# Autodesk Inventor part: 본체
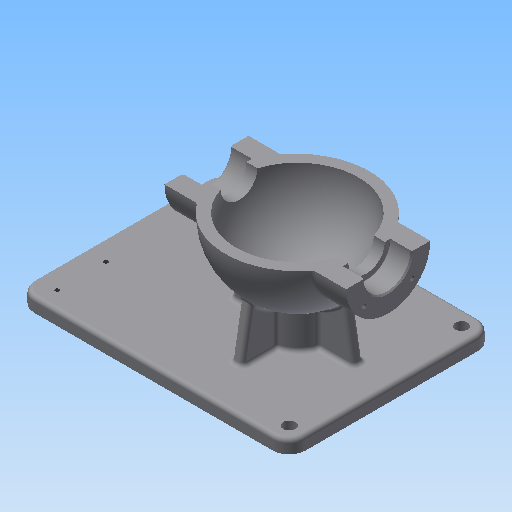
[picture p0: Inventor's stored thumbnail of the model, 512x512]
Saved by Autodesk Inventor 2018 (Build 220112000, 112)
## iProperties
Created: 2015-12
Part Number: 본체
Material: 일반
Document SubType Name: Modeling
Designer: mduedu
Density: 1 g/cm^3
Mass: 491.008 g
Surface Area: 1128.56 cm^2
Volume: 491.008 cm^3
Appearance: 기본값
Author: mduedu
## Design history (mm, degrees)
sketch "스케치1"
  geometry: L1 (-53, 0)-(53, 0); A1 r 53 centre (0, 0) between (53, 0) and (-53, 0); 2 further points
  constraints: 2 coincident, 2 end point, 2 point on circle, 1 centre point, 1 horizontal, 1 midpoint
  dimensions: "d0" = 53 radius of A1
revolve "회전1" sketch "스케치1" stored, may be unused: angle "d2" = 90 deg
feature "쉘1" dims "d11" = 8
node "작업 평면1"
sketch "스케치2"
  geometry: C1 r 31 at (0, 0); 1 further point
  constraints: 1 centre point, 1 coincident
  dimensions: "d4" = 62 diameter of C1
extrude "돌출1" join sketch "스케치2" stored distance "d5" = 10; taper "d6" = 0 deg
hole "구멍1" diameter "d14" = 35; stored, may be unused: countersink angle "d18" = 90 deg, drill point angle "d20" = 0 deg; dims "d12" = 10, "d13" = 10, "d15" = 6, "d16" = 4, "d17" = 2, "d19" = 16
hole "구멍2" diameter "d23" = 27; stored, may be unused: countersink angle "d27" = 90 deg, drill point angle "d29" = 0 deg; dims "d21" = 10, "d22" = 10, "d24" = 6, "d25" = 4, "d26" = 2, "d28" = 16
fillet "모깎기1" dims "d30" = 0.3
chamfer "모따기1" distance "d40" = 1; stored, may be unused: second distance "d41" = 2, angle "d42" = 45 deg
sketch "스케치4"
  geometry: L1 (0, 0)-(0, -25); L2 (0, 0)-(-17.678, -17.678); A1 r 25 centre (0, 0) between (-17.678, -17.678) and (0, -25); 1 further point
  constraints: 4 end point, 2 point on circle, 1 centre point, 1 coincident, 1 vertical
  dimensions: "d43" = 50 diameter of A1; "d47" = 45 deg angle of L1 L2
hole "구멍4" sketch "스케치4" at (-17.678, -17.678) diameter "d49" = 3.242; stored, may be unused: countersink angle "d53" = 90 deg, drill point angle "d55" = 118 deg; dims "d50" = 11, "d51" = 4, "d52" = 2, "d54" = 13
node "작업 평면3"
sketch "스케치6" dims "d21" = 10, "d22" = 10
  geometry: L1 (-70, -75)-(130, -75); L2 (130, -75)-(130, 76); L3 (130, 76)-(-70, 76); L4 (-70, 76)-(-70, -75); 2 further points
  constraints: 8 end point, 2 parallel, 1 coincident, 1 horizontal, 1 perpendicular
  dimensions: "d158" = 200 distance of L3.end L2.end; "d159" = 151 distance of L2.end L1.end; "d162" = 75 distance from line of L1 point (0, 0); "d163" = 70 distance from line of L4 point (0, 0)
extrude "돌출3" join sketch "스케치6" distance "d80" = 10; taper "d81" = 0 deg
sketch "스케치7"
  geometry: C1 r 20 at (0, 0); 2 further points
  constraints: 2 coincident, 1 centre point
  dimensions: "d82" = 40 diameter of C1
extrude "돌출4" join sketch "스케치7" stored distance "d84" = 10; taper "d85" = 0 deg
sketch "스케치8"
  geometry: 3 further points
  constraints: 2 coincident
hole "구멍6" sketch "스케치8" at (0, 0) diameter "d86" = 20; stored, may be unused: countersink angle "d90" = 90 deg, drill point angle "d92" = 118 deg; dims "d87" = 7, "d88" = 40, "d89" = 5, "d91" = 10
fillet "모깎기2" dims "d93" = 0.3
sketch "스케치9"
  geometry: L1 (-45, -75)-(-38.245, -36.692); L2 (70, -75)-(-130, -75) reference; A1 r 53 centre (0, 0) between (42.988, 31) and (42.988, -31) reference; 1 further point
  constraints: 2 end point, 1 coincident, 1 point on circle, 1 point on line
  dimensions: "d94" = 45 horizontal distance of L1.start point (0, 0); "d160" = 80 deg angle of L2 L1
feature "리브1" sketch "스케치9" dims "d96" = 1, "d97" = 8, "d98" = 0, "d99" = 0, "d100" = 1, "d101" = 1
fillet "모깎기3" dims "d120" = 3
fillet "모깎기4" dims "d121" = 3, "d122" = 3
fillet "모깎기5" dims "d123" = 3
sketch "스케치12"
  geometry: L1 (0, 100)-(0, -100); L2 (0, 100)-(100, 100); L3 (100, 100)-(100, -100); L4 (100, -100)-(0, -100); 2 further points
  constraints: 8 end point, 3 perpendicular, 1 coincident, 1 midpoint, 1 vertical
  dimensions: "d127" = 200 distance of L2.end L3.end; "d129" = 100 distance between parallel lines of L1 L3
extrude "돌출5" cut sketch "스케치12" extent not by distance; stored distance "d130" = 10; taper "d131" = 0 deg
fillet "모깎기10" dims "d164" = 12
fillet "모깎기11" dims "d165" = 3
sketch "스케치15"
  geometry: C1 r 4.5 at (-118, 63); C2 r 4.5 at (58, 63); C3 r 4.5 at (58, -64); A1 r 12 centre (-118, 63) between (-118, 75) and (-130, 63) reference; A2 r 12 centre (58, 63) between (70, 63) and (58, 75) reference; A3 r 12 centre (58, -64) between (58, -76) and (70, -64) reference; 1 further point
  constraints: 3 centre point, 3 coincident, 2 equal radius
  dimensions: "d166" = 9 diameter of C1
extrude "돌출8" cut sketch "스케치15" extent not by distance; stored distance "d167" = 10; taper "d168" = 0 deg
sketch "스케치16"
  geometry: L1 (-130, 63)-(-130, -64) reference; L2 (-118, -76)-(58, -76) reference; 2 further points
  constraints: 1 other
  dimensions: "d169" = 60 distance from line of point (-70, 54) L1; "d170" = 130 distance from line of point (-70, 54) L2
feature "엠보싱2" sketch "스케치16" dims "d171" = 0.5, "d172" = 0
sketch "스케치17"
  geometry: L1 (-118, 76)-(58, 76) reference; L2 (-130, -63)-(-130, 64) reference; 2 further points
  constraints: 1 vertical alignment
  dimensions: "d180" = 13 distance from line of L1 point (-114, 63); "d181" = 16 distance from line of point (-114, 63) L2; "d182" = 36 distance of point (-114, 27) point (-114, 63)
hole "구멍9" sketch "스케치17" at (-114, 63), (-114, 27) diameter "d173" = 3.242; stored, may be unused: countersink angle "d177" = 90 deg, drill point angle "d179" = 0 deg; dims "d174" = 6, "d175" = 4, "d176" = 2, "d178" = 8
node "솔리드1"
mirror "대칭1"
mirror "대칭2"
pattern_circular "원형 패턴1" dims angle "d57" = 360 deg
mirror "대칭3"
pattern_circular "원형 패턴3" dims angle "d103" = 360 deg
other parameters: "d3" = 67, "d77" = -85
